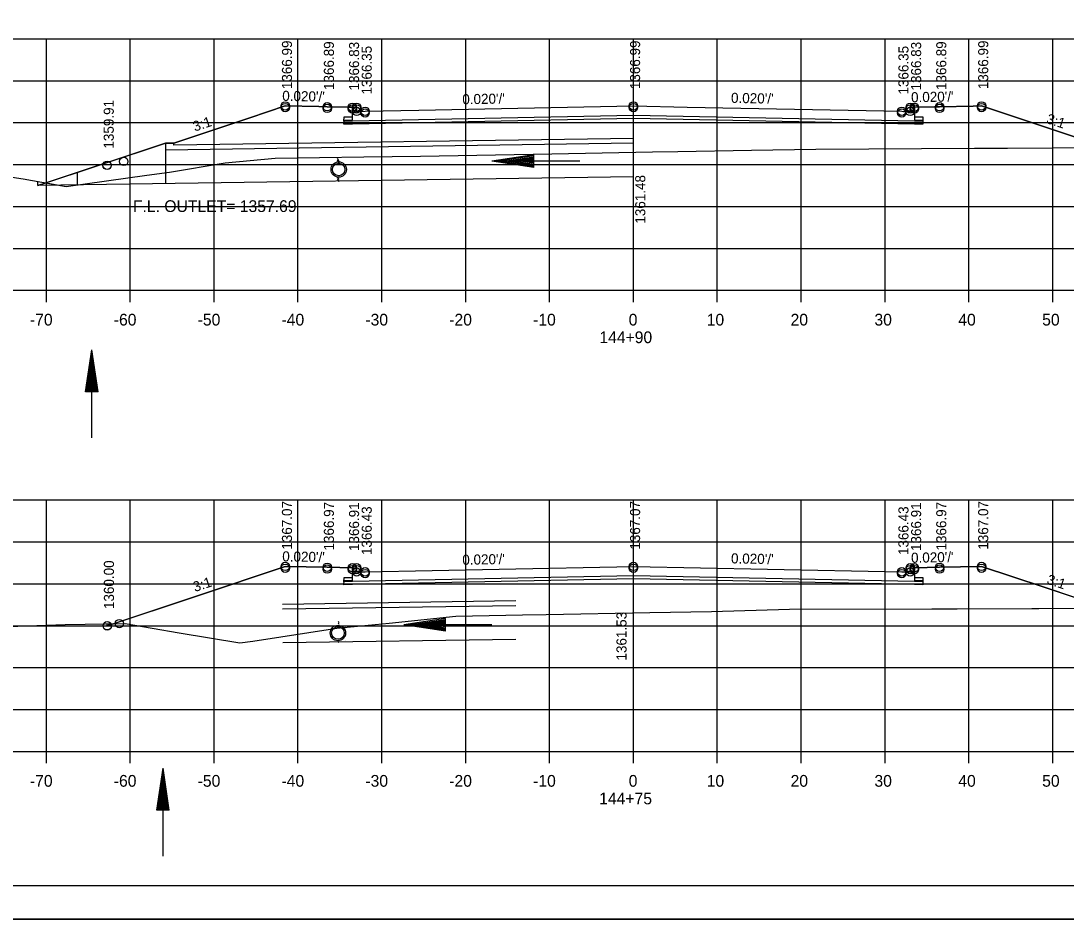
# Model space of a CAD drawing. Extents: x 1374311 to 1383814, y 384102 to 406278.
# Drawn here: x 1381555.6 to 1381680.3, y 390298.1 to 390405.2 of the extents above; entities that cross this region are included whole.
import ezdxf

# ---------------------------------------------------------------- set-up
doc = ezdxf.new("R2010")
doc.units = 0
for name, color, linetype in [('R_Axis', 7, 'Continuous'), ('R_Axis Annot', 7, 'Continuous'), ('R_Border', 7, 'Continuous'), ('R_Draft', 7, 'Continuous'), ('R_Exist Surface', 7, 'Continuous'), ('R_Fin Surface', 7, 'Continuous'), ('R_Grid', 7, 'Continuous'), ('R_No Plot', 7, 'Continuous'), ('R_Water', 7, 'Continuous'), ('R_Xsect Elev', 7, 'Continuous'), ('R_Xsect Slope', 7, 'Continuous')]:
    doc.layers.add(name, color=color, linetype=linetype)

msp = doc.modelspace()

# ---------------------------------------------------------------- linework, layer by layer
at = {"layer": 'R_Axis'}
for p, q in [((1381488.66, 390373.05), (1381768.66, 390373.05)), ((1381558.66, 390371.65), (1381558.66, 390373.05)), ((1381568.66, 390371.65), (1381568.66, 390373.05)), ((1381578.66, 390371.65), (1381578.66, 390373.05)), ((1381588.66, 390371.65), (1381588.66, 390373.05)), ((1381598.66, 390371.65), (1381598.66, 390373.05)), ((1381608.66, 390371.65), (1381608.66, 390373.05)), ((1381618.66, 390371.65), (1381618.66, 390373.05)), ((1381628.66, 390371.65), (1381628.66, 390373.05)), ((1381638.66, 390371.65), (1381638.66, 390373.05)), ((1381648.66, 390371.65), (1381648.66, 390373.05)), ((1381658.66, 390371.65), (1381658.66, 390373.05)), ((1381668.66, 390371.65), (1381668.66, 390373.05)), ((1381678.66, 390371.65), (1381678.66, 390373.05)), ((1381488.66, 390318.05), (1381768.66, 390318.05)), ((1381558.66, 390316.65), (1381558.66, 390318.05)), ((1381568.66, 390316.65), (1381568.66, 390318.05)), ((1381578.66, 390316.65), (1381578.66, 390318.05)), ((1381588.66, 390316.65), (1381588.66, 390318.05)), ((1381598.66, 390316.65), (1381598.66, 390318.05)), ((1381608.66, 390316.65), (1381608.66, 390318.05)), ((1381618.66, 390316.65), (1381618.66, 390318.05)), ((1381628.66, 390316.65), (1381628.66, 390318.05)), ((1381638.66, 390316.65), (1381638.66, 390318.05)), ((1381648.66, 390316.65), (1381648.66, 390318.05)), ((1381658.66, 390316.65), (1381658.66, 390318.05)), ((1381668.66, 390316.65), (1381668.66, 390318.05)), ((1381678.66, 390316.65), (1381678.66, 390318.05))]:
    msp.add_line(p, q, dxfattribs=at)
at = {"layer": 'R_Border'}
msp.add_line((1381786.84, 390302.05), (1381470.66, 390302.05), dxfattribs=at)
at = {"layer": 'R_Draft'}
for p, q in [((1381616.78, 390389.19), (1381611.78, 390388.44)), ((1381616.78, 390387.69), (1381611.78, 390388.44)), ((1381616.78, 390389.07), (1381612.61, 390388.44)), ((1381616.78, 390387.82), (1381612.61, 390388.44)), ((1381616.78, 390388.94), (1381613.47, 390388.44)), ((1381616.78, 390387.94), (1381613.47, 390388.44)), ((1381616.78, 390388.81), (1381614.31, 390388.44)), ((1381616.78, 390388.07), (1381614.31, 390388.44)), ((1381616.78, 390388.69), (1381615.15, 390388.44)), ((1381616.78, 390388.2), (1381615.15, 390388.44)), ((1381616.78, 390388.56), (1381615.99, 390388.44)), ((1381616.78, 390388.32), (1381615.99, 390388.44)), ((1381616.78, 390387.69), (1381616.78, 390389.19)), ((1381563.32, 390360.96), (1381564.07, 390365.96)), ((1381564.82, 390360.96), (1381564.07, 390365.96)), ((1381563.44, 390360.96), (1381564.07, 390365.13)), ((1381564.69, 390360.96), (1381564.07, 390365.13)), ((1381563.57, 390360.96), (1381564.07, 390364.27)), ((1381563.7, 390360.96), (1381564.07, 390363.43)), ((1381564.57, 390360.96), (1381564.07, 390364.27)), ((1381564.44, 390360.96), (1381564.07, 390363.43)), ((1381563.82, 390360.96), (1381564.07, 390362.59)), ((1381564.31, 390360.96), (1381564.07, 390362.59)), ((1381564.82, 390360.96), (1381563.32, 390360.96)), ((1381563.95, 390360.96), (1381564.07, 390361.75)), ((1381564.19, 390360.96), (1381564.07, 390361.75)), ((1381606.27, 390333.9), (1381601.27, 390333.15)), ((1381606.27, 390333.77), (1381602.1, 390333.15)), ((1381606.27, 390333.64), (1381602.96, 390333.15)), ((1381606.27, 390333.52), (1381603.8, 390333.15)), ((1381606.27, 390332.4), (1381606.27, 390333.9)), ((1381606.27, 390332.4), (1381601.27, 390333.15)), ((1381606.27, 390332.52), (1381602.1, 390333.15)), ((1381606.27, 390332.65), (1381602.96, 390333.15)), ((1381606.27, 390332.77), (1381603.8, 390333.15)), ((1381606.27, 390333.39), (1381604.64, 390333.15)), ((1381606.27, 390332.9), (1381604.64, 390333.15)), ((1381606.27, 390333.26), (1381605.48, 390333.15)), ((1381606.27, 390333.03), (1381605.48, 390333.15)), ((1381571.82, 390311.06), (1381572.57, 390316.06)), ((1381573.32, 390311.06), (1381572.57, 390316.06)), ((1381571.94, 390311.06), (1381572.57, 390315.22)), ((1381573.19, 390311.06), (1381572.57, 390315.22)), ((1381572.07, 390311.06), (1381572.57, 390314.36)), ((1381572.19, 390311.06), (1381572.57, 390313.53)), ((1381573.06, 390311.06), (1381572.57, 390314.36)), ((1381572.94, 390311.06), (1381572.57, 390313.53)), ((1381572.32, 390311.06), (1381572.57, 390312.68)), ((1381572.81, 390311.06), (1381572.57, 390312.68)), ((1381573.32, 390311.06), (1381571.82, 390311.06)), ((1381572.45, 390311.06), (1381572.57, 390311.85)), ((1381572.68, 390311.06), (1381572.57, 390311.85))]:
    msp.add_line(p, q, dxfattribs=at)
at = {"layer": 'R_Exist Surface'}
for p, q in [((1381593.34, 390388.81), (1381593.53, 390388.45)), ((1381593.34, 390386.39), (1381593.53, 390386.04)), ((1381593.46, 390333.59), (1381593.53, 390333.45)), ((1381594.36, 390332.92), (1381594.36, 390332.91)), ((1381593.46, 390331.17), (1381593.53, 390331.04)), ((1381594.36, 390331.09), (1381594.36, 390331.08))]:
    msp.add_line(p, q, dxfattribs=at)
for points in [[(1381544.65, 390388.04), (1381555.9, 390386.35), (1381561.04, 390385.45), (1381570.66, 390386.77), (1381573.34, 390387.15), (1381579.98, 390388.25), (1381585.96, 390388.8), (1381596.53, 390388.96), (1381603.29, 390389.06), (1381618.94, 390389.34), (1381630.94, 390389.56), (1381633.94, 390389.62), (1381642.73, 390389.78), (1381650.4, 390389.89), (1381669.35, 390390), (1381673.27, 390390.01), (1381678.64, 390390.03), (1381693.66, 390390.11)], [(1381554.16, 390332.97), (1381560.92, 390333.18), (1381568.05, 390333.32), (1381574.5, 390332.21), (1381581.73, 390331.01), (1381583.29, 390331.22), (1381593.28, 390332.75), (1381593.66, 390332.8), (1381593.7, 390332.81), (1381599.54, 390333.34), (1381607.49, 390334.2), (1381615.42, 390334.34), (1381618.24, 390334.4), (1381630.62, 390334.61), (1381637.97, 390334.75), (1381647.26, 390335.01), (1381664.24, 390335.05), (1381664.92, 390335.05), (1381667.25, 390335.05), (1381686.73, 390335.16)]]:
    msp.add_lwpolyline(points, dxfattribs=at)
for centre in [(1381593.52, 390387.46), (1381593.43, 390332.18)]:
    msp.add_circle(centre, 0.917, dxfattribs=at)
at = {"layer": 'R_Fin Surface'}
for points in [[(1381557.64, 390385.54), (1381572.85, 390390.61), (1381573.85, 390390.61), (1381582.91, 390393.63), (1381587.15, 390395.04), (1381591.15, 390394.96), (1381592.15, 390394.94), (1381594.55, 390394.89), (1381595.15, 390394.88), (1381595.25, 390394.88), (1381595.65, 390394.88), (1381595.66, 390394.48), (1381595.66, 390394.38), (1381595.86, 390394.38), (1381596.66, 390394.4), (1381603.06, 390394.53), (1381628.66, 390395.04), (1381635.06, 390394.91), (1381660.66, 390394.4), (1381660.86, 390394.39), (1381661.66, 390394.38), (1381661.67, 390394.78), (1381661.67, 390394.88), (1381661.77, 390394.88), (1381662.17, 390394.88), (1381664.57, 390394.93), (1381665.17, 390394.94), (1381669.17, 390395.02), (1381670.17, 390395.04), (1381682.09, 390391.07)], [(1381662.17, 390394.52), (1381662.18, 390393.37), (1381663.18, 390393.36), (1381663.17, 390392.86), (1381662.17, 390392.88), (1381628.66, 390393.55), (1381595.15, 390392.88), (1381594.15, 390392.86), (1381594.16, 390393.36), (1381595.16, 390393.37), (1381595.15, 390394.52)], [(1381565.92, 390333.04), (1381576.55, 390336.59), (1381587.15, 390340.12), (1381589.65, 390340.07), (1381592.15, 390340.02), (1381593.65, 390339.99), (1381595.15, 390339.96), (1381595.4, 390339.96), (1381595.65, 390339.96), (1381595.65, 390339.71), (1381595.66, 390339.46), (1381596.16, 390339.47), (1381596.66, 390339.48), (1381612.66, 390339.8), (1381628.66, 390340.12), (1381644.66, 390339.8), (1381660.66, 390339.48), (1381661.16, 390339.47), (1381661.66, 390339.46), (1381661.66, 390339.71), (1381661.67, 390339.96), (1381661.92, 390339.96), (1381662.17, 390339.96), (1381663.67, 390339.99), (1381665.17, 390340.02), (1381667.67, 390340.07), (1381670.17, 390340.12), (1381677.62, 390337.64), (1381685.24, 390335.09)], [(1381662.17, 390339.6), (1381662.18, 390338.45), (1381663.18, 390338.44), (1381663.17, 390337.94), (1381662.17, 390337.96), (1381628.66, 390338.63), (1381595.15, 390337.96), (1381594.15, 390337.94), (1381594.16, 390338.44), (1381595.16, 390338.45), (1381595.15, 390339.6)]]:
    msp.add_lwpolyline(points, dxfattribs=at)
at = {"layer": 'R_Grid'}
for p, q in [((1381488.66, 390403.05), (1381768.66, 390403.05)), ((1381558.66, 390373.05), (1381558.66, 390403.05)), ((1381568.66, 390373.05), (1381568.66, 390403.05)), ((1381578.66, 390373.05), (1381578.66, 390403.05)), ((1381588.66, 390373.05), (1381588.66, 390403.05)), ((1381598.66, 390373.05), (1381598.66, 390403.05)), ((1381608.66, 390373.05), (1381608.66, 390403.05)), ((1381618.66, 390373.05), (1381618.66, 390403.05)), ((1381628.66, 390373.05), (1381628.66, 390403.05)), ((1381638.66, 390373.05), (1381638.66, 390403.05)), ((1381648.66, 390373.05), (1381648.66, 390403.05)), ((1381658.66, 390373.05), (1381658.66, 390403.05)), ((1381668.66, 390373.05), (1381668.66, 390403.05)), ((1381678.66, 390373.05), (1381678.66, 390403.05)), ((1381488.66, 390398.05), (1381768.66, 390398.05)), ((1381488.66, 390393.05), (1381768.66, 390393.05)), ((1381488.66, 390388.05), (1381768.66, 390388.05)), ((1381488.66, 390383.05), (1381768.66, 390383.05)), ((1381488.66, 390378.05), (1381768.66, 390378.05)), ((1381488.66, 390373.05), (1381768.66, 390373.05)), ((1381488.66, 390348.05), (1381768.66, 390348.05)), ((1381558.66, 390318.05), (1381558.66, 390348.05)), ((1381568.66, 390318.05), (1381568.66, 390348.05)), ((1381578.66, 390318.05), (1381578.66, 390348.05)), ((1381588.66, 390318.05), (1381588.66, 390348.05)), ((1381598.66, 390318.05), (1381598.66, 390348.05)), ((1381608.66, 390318.05), (1381608.66, 390348.05)), ((1381618.66, 390318.05), (1381618.66, 390348.05)), ((1381628.66, 390318.05), (1381628.66, 390348.05)), ((1381638.66, 390318.05), (1381638.66, 390348.05)), ((1381648.66, 390318.05), (1381648.66, 390348.05)), ((1381658.66, 390318.05), (1381658.66, 390348.05)), ((1381668.66, 390318.05), (1381668.66, 390348.05)), ((1381678.66, 390318.05), (1381678.66, 390348.05)), ((1381488.66, 390343.05), (1381768.66, 390343.05)), ((1381488.66, 390338.05), (1381768.66, 390338.05)), ((1381488.66, 390333.05), (1381768.66, 390333.05)), ((1381488.66, 390328.05), (1381768.66, 390328.05)), ((1381488.66, 390323.05), (1381768.66, 390323.05)), ((1381488.66, 390318.05), (1381768.66, 390318.05))]:
    msp.add_line(p, q, dxfattribs=at)
at = {"layer": 'R_No Plot'}
msp.add_line((1381458.26, 390298.07), (1381791.59, 390298.07), dxfattribs=at)
for points in [[(1381458.25, 390511.4), (1381791.59, 390511.4), (1381791.59, 390298.06), (1381458.25, 390298.06)], [(1381704.58, 390507.51), (1381704.58, 390497.63), (1381740.31, 390497.63), (1381740.31, 390494.71), (1381763.51, 390494.71), (1381763.51, 390471.49), (1381786.84, 390471.49), (1381786.84, 390302.05), (1381470.66, 390302.05), (1381470.66, 390507.51)], [(1381557.64, 390385.54), (1381557.64, 390386.04), (1381558.64, 390385.87)], [(1381566.67, 390333.29), (1381568.05, 390333.32), (1381574.5, 390332.21), (1381581.73, 390331.01), (1381583.29, 390331.22), (1381593.28, 390332.75), (1381593.66, 390332.8), (1381593.7, 390332.81), (1381599.54, 390333.34), (1381607.49, 390334.2), (1381615.42, 390334.34), (1381618.24, 390334.4), (1381630.62, 390334.61), (1381637.97, 390334.75), (1381647.26, 390335.01), (1381664.24, 390335.05), (1381664.92, 390335.05), (1381667.25, 390335.05), (1381685.09, 390335.15), (1381677.62, 390337.64), (1381670.17, 390340.12), (1381667.67, 390340.07), (1381665.17, 390340.02), (1381663.67, 390339.99), (1381662.17, 390339.96), (1381662.18, 390338.81), (1381663.18, 390338.8), (1381663.17, 390338.3), (1381662.17, 390338.32), (1381628.66, 390338.99), (1381595.15, 390338.32), (1381594.15, 390338.3), (1381594.16, 390338.8), (1381595.16, 390338.81), (1381595.15, 390339.96), (1381593.65, 390339.99), (1381592.15, 390340.02), (1381589.65, 390340.07), (1381587.15, 390340.12), (1381576.55, 390336.59)], [(1381565.92, 390333.04), (1381565.92, 390333.28), (1381566.67, 390333.29)]]:
    msp.add_lwpolyline(points, close=True, dxfattribs=at)
msp.add_lwpolyline([(1381682.09, 390391.07), (1381670.17, 390395.04), (1381669.17, 390395.02), (1381665.17, 390394.94), (1381664.57, 390394.93), (1381662.17, 390394.88), (1381662.18, 390393.73), (1381663.18, 390393.72), (1381663.17, 390393.22), (1381662.17, 390393.24), (1381628.66, 390393.91), (1381595.15, 390393.24), (1381594.15, 390393.22), (1381594.16, 390393.72), (1381595.16, 390393.73), (1381595.15, 390394.88), (1381594.55, 390394.89), (1381592.15, 390394.94), (1381591.15, 390394.96), (1381587.15, 390395.04), (1381582.91, 390393.63), (1381573.85, 390390.61), (1381572.85, 390390.61), (1381558.64, 390385.87), (1381561.04, 390385.45), (1381570.66, 390386.77), (1381573.34, 390387.15), (1381579.98, 390388.25), (1381585.96, 390388.8), (1381596.53, 390388.96), (1381603.29, 390389.06), (1381618.94, 390389.34), (1381630.94, 390389.56), (1381633.94, 390389.62), (1381642.73, 390389.78), (1381650.4, 390389.89), (1381669.35, 390390), (1381673.27, 390390.01), (1381678.64, 390390.03), (1381685.08, 390390.07)], dxfattribs=at)
for centre in [(1381587.15, 390395.04), (1381587.15, 390395.04), (1381587.15, 390394.84), (1381592.15, 390394.94), (1381592.15, 390394.94), (1381592.15, 390394.74), (1381595.15, 390394.88), (1381595.15, 390394.88), (1381595.15, 390394.68), (1381595.65, 390394.88), (1381595.65, 390394.88), (1381595.65, 390394.68), (1381595.66, 390394.38), (1381596.66, 390394.4), (1381596.66, 390394.4), (1381596.66, 390394.2), (1381628.66, 390395.04), (1381628.66, 390395.04), (1381628.66, 390394.84), (1381660.66, 390394.4), (1381660.66, 390394.4), (1381660.66, 390394.2), (1381661.66, 390394.38), (1381661.67, 390394.88), (1381661.67, 390394.88), (1381661.67, 390394.68), (1381662.17, 390394.88), (1381662.17, 390394.88), (1381662.17, 390394.68), (1381665.17, 390394.94), (1381665.17, 390394.94), (1381665.17, 390394.74), (1381670.17, 390395.04), (1381670.17, 390395.04), (1381670.17, 390394.84), (1381565.9, 390387.96), (1381565.9, 390387.96), (1381565.9, 390387.95), (1381565.9, 390387.95), (1381567.89, 390388.42), (1381567.89, 390388.42), (1381587.15, 390340.12), (1381587.15, 390340.12), (1381587.15, 390339.91), (1381592.15, 390340.02), (1381592.15, 390340.02), (1381592.15, 390339.81), (1381595.15, 390339.96), (1381595.15, 390339.96), (1381595.15, 390339.75), (1381595.65, 390339.96), (1381595.65, 390339.96), (1381595.65, 390339.75), (1381595.66, 390339.46), (1381596.66, 390339.48), (1381596.66, 390339.48), (1381596.66, 390339.27), (1381628.66, 390340.12), (1381628.66, 390340.12), (1381628.66, 390339.91), (1381660.66, 390339.48), (1381660.66, 390339.48), (1381660.66, 390339.27), (1381661.66, 390339.46), (1381661.67, 390339.96), (1381661.67, 390339.96), (1381661.67, 390339.75), (1381662.17, 390339.96), (1381662.17, 390339.96), (1381662.17, 390339.75), (1381665.17, 390340.02), (1381665.17, 390340.02), (1381665.17, 390339.81), (1381670.17, 390340.12), (1381670.17, 390340.12), (1381670.17, 390339.91), (1381565.92, 390333.05), (1381565.92, 390333.05), (1381565.92, 390333.04), (1381565.92, 390333.04), (1381567.36, 390333.31), (1381567.36, 390333.31)]:
    msp.add_circle(centre, 0.5, dxfattribs=at)
at = {"layer": 'R_Water'}
for p, q in [((1381628.66, 390391.17), (1381573.85, 390390.36)), ((1381572.85, 390390.61), (1381572.85, 390385.73)), ((1381573.85, 390390.61), (1381572.85, 390390.61)), ((1381628.66, 390390.59), (1381572.85, 390389.76)), ((1381573.85, 390390.36), (1381573.85, 390390.61)), ((1381593.34, 390388.6), (1381593.53, 390388.25)), ((1381622.28, 390388.44), (1381611.78, 390388.44)), ((1381562.35, 390387.11), (1381562.35, 390385.61)), ((1381628.66, 390386.59), (1381557.64, 390385.54)), ((1381593.34, 390386.6), (1381593.53, 390386.25)), ((1381564.07, 390355.46), (1381564.07, 390365.96)), ((1381614.66, 390336), (1381586.81, 390335.59)), ((1381614.66, 390335.42), (1381586.82, 390335.01)), ((1381593.46, 390333.38), (1381593.53, 390333.25)), ((1381594.36, 390332.76), (1381594.36, 390332.75)), ((1381611.77, 390333.15), (1381601.27, 390333.15)), ((1381614.66, 390331.42), (1381586.87, 390331.01)), ((1381593.46, 390331.38), (1381593.53, 390331.25)), ((1381594.36, 390331.26), (1381594.36, 390331.25)), ((1381572.57, 390305.55), (1381572.57, 390316.06))]:
    msp.add_line(p, q, dxfattribs=at)
for centre in [(1381593.52, 390387.46), (1381593.43, 390332.18)]:
    msp.add_circle(centre, 0.75, dxfattribs=at)

# ---------------------------------------------------------------- texts
at = {"layer": 'R_Axis Annot'}
for s, p in [('-70', (1381556.7, 390368.85)), ('-60', (1381566.7, 390368.85)), ('-50', (1381576.7, 390368.85)), ('-40', (1381586.7, 390368.85)), ('-30', (1381596.7, 390368.85)), ('-20', (1381606.7, 390368.85)), ('-10', (1381616.7, 390368.85)), ('0', (1381628.1, 390368.85)), ('10', (1381637.4, 390368.85)), ('20', (1381647.4, 390368.85)), ('30', (1381657.4, 390368.85)), ('40', (1381667.4, 390368.85)), ('50', (1381677.4, 390368.85)), ('144+90', (1381624.6, 390366.75)), ('-70', (1381556.7, 390313.85)), ('-60', (1381566.7, 390313.85)), ('-50', (1381576.7, 390313.85)), ('-40', (1381586.7, 390313.85)), ('-30', (1381596.7, 390313.85)), ('-20', (1381606.7, 390313.85)), ('-10', (1381616.7, 390313.85)), ('0', (1381628.1, 390313.85)), ('10', (1381637.4, 390313.85)), ('20', (1381647.4, 390313.85)), ('30', (1381657.4, 390313.85)), ('40', (1381667.4, 390313.85)), ('50', (1381677.4, 390313.85)), ('144+75', (1381624.58, 390311.75))]:
    msp.add_text(s, height=1.4, dxfattribs=at).set_placement(p)
at = {"layer": 'R_Water'}
msp.add_text('F.L. OUTLET= 1357.69', height=1.4, dxfattribs=at).set_placement((1381568.98, 390382.39))
at = {"layer": 'R_Xsect Elev'}
for s, p in [('1366.99', (1381587.95, 390397.04)), ('1366.89', (1381592.95, 390396.94)), ('1366.83', (1381595.95, 390396.88)), ('1366.35', (1381597.46, 390396.4)), ('1366.99', (1381629.46, 390397.04)), ('1366.35', (1381661.46, 390396.4)), ('1366.83', (1381662.97, 390396.88)), ('1366.89', (1381665.97, 390396.94)), ('1366.99', (1381670.97, 390397.04)), ('1359.91', (1381566.7, 390389.95)), ('1361.48', (1381630.08, 390381)), ('1367.07', (1381587.95, 390342.12)), ('1366.97', (1381592.95, 390342.02)), ('1366.91', (1381595.95, 390341.96)), ('1366.43', (1381597.46, 390341.48)), ('1367.07', (1381629.46, 390342.12)), ('1366.43', (1381661.46, 390341.48)), ('1366.91', (1381662.97, 390341.96)), ('1366.97', (1381665.97, 390342.02)), ('1367.07', (1381670.97, 390342.12)), ('1360.00', (1381566.72, 390335.04)), ('1361.53', (1381627.84, 390328.9))]:
    msp.add_text(s, height=1.2, rotation=90, dxfattribs=at).set_placement(p)
at = {"layer": 'R_Xsect Slope'}
for s, rotation, p in [("0.020'/'", 358.8542, (1381586.78, 390395.65)), ("0.020'/'", 1.1458, (1381608.27, 390395.23)), ("0.020'/'", 358.8542, (1381640.29, 390395.41)), ("0.020'/'", 1.1458, (1381661.78, 390395.47)), ('3:1', 18.4349, (1381576.36, 390391.97)), ('3:1', 341.5651, (1381677.81, 390393.02)), ("0.020'/'", 358.8542, (1381586.78, 390340.73)), ("0.020'/'", 1.1458, (1381608.27, 390340.31)), ("0.020'/'", 358.8542, (1381640.29, 390340.49)), ("0.020'/'", 1.1458, (1381661.78, 390340.55)), ('3:1', 18.4349, (1381576.38, 390337.06)), ('3:1', 341.5651, (1381677.86, 390338.08))]:
    msp.add_text(s, height=1.2, rotation=rotation, dxfattribs=at).set_placement(p)

doc.saveas('drawing.dxf')
